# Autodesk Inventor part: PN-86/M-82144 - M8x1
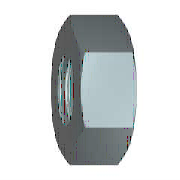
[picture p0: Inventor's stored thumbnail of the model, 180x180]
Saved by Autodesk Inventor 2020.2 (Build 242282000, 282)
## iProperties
Manager: www.cadconsulting.pl
Company: Fabian Stasiak CAD Consulting
Created: 2006-02
Part Number: PN-86/M-82144 - M8x1
Material: Stal, miękka
Description: Nakrętka
Document SubType Name: Modeling
Standard: PN-86/M-82144
Designer: F.Stasiak
Standards Organization: PN
Language: pl-PL
Size Designation: M8x1
Categories: <MemberInstance><Categories><Category DisplayName="Mocowania" InternalName="e4da775c-781d-43d5-af7c-5136215cf5a6" Mnemonic="FSTN"><Category DisplayName="Nakrętk
Density: 7.86 g/cm^3
Mass: 5.74624 g
Surface Area: 6.48179 cm^2
Volume: 0.731074 cm^3
Appearance: Metal-Stal
Author: F.Stasiak
Subject: Zbiór ćwiczeń. Autodesk Inventor 2020. Kurs podstawowy
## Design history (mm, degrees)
sketch "Szkic1"
  geometry: L1 (-7.506, 0)-(-3.753, 6.5); L2 (-3.753, 6.5)-(3.753, 6.5); L3 (3.753, 6.5)-(7.506, 0); L4 (7.506, 0)-(3.753, -6.5); L5 (3.753, -6.5)-(-3.753, -6.5); L6 (-3.753, -6.5)-(-7.506, 0); 2 further points
  constraints: 12 end point, 1 coincident, 1 horizontal, 11 other
  dimensions: "d0" = 15.01111 distance of L3.end L1.start (= 1.1547 x SW)
extrude "Bryła" new body sketch "Szkic1" distance "d1" = 6.8 (= KOH); taper "d2" = 0 deg
sketch "Szkic2"
  geometry: L1 (0, 3.753)-(0, 7.506) reference; L2 (0, 7.506)-(6.8, 7.506) reference; L3 (6.8, 3.753)-(6.8, 7.506) reference; L4 (-0.68, 0)-(8.84, 0) reference; L5 (0.581, 7.506)-(0, 6.5); L6 (6.219, 7.506)-(6.8, 6.5)
  constraints: 4 end point, 4 point on line
  dimensions: "d3" = 30 deg angle of L1 L5 (= ANG1); "d4" = 30 deg angle of L3 L6 (= ANG2); "d5" = 13 diameter of L5.end L4 (= SW0); "d6" = 13 diameter of L6.end L4 (= SW01)
revolve "Faza1" sketch "Szkic2" stored, may be unused: angle "d7" = 90 deg
sketch "Szkic3"
  geometry: A1 r 6.5 centre (0, 0) between (-3.25, -5.629) and (3.25, -5.629) reference; 1 further point
  constraints: 1 coincident
hole "Gwint" sketch "Szkic3" at (0, 0) diameter "d25" = 6.917; stored, may be unused: countersink angle "d29" = 82 deg, drill point angle "d31" = 118 deg; dims "d26" = 6, "d27" = 4, "d28" = 2, "d30" = 8
workaxis "Work Axis1"
workplane "Work Plane1"
node "Bryła1"
node "Korpusy bryłowe"
node "Korpusy powierzchniowe"
chamfer "Faza2" distance "d8" = 0.54127 (= -0.5 x GD1 + 0.5 x NND); stored, may be unused: angle "d9" = 30 deg, second distance "d40" = 0.54127 (= -0.5 x GD1 + 0.5 x NND)
chamfer "Faza3" distance "d10" = 0.54127 (= -0.5 x GD1 + 0.5 x NND); stored, may be unused: angle "d11" = 30 deg, second distance "d41" = 0.54127 (= -0.5 x GD1 + 0.5 x NND)
other parameters: "ANG1" = 30 deg [user parameter; used in 1 equation term], "ANG2" = 30 deg [user parameter; used in 1 equation term], "NND" = 8 [user parameter; used in 4 equation terms], "KOH" = 6.8 [user parameter; used in 1 equation term], "SW" = 13 [user parameter; used in 4 equation terms], "SW0" = 13 (= SW) [user parameter; used in 1 equation term], "SW01" = 13 (= SW) [user parameter; used in 1 equation term], "GD1" = 6.91747 (computed from THREADDIA, PTC, TOA) [user parameter; used in 4 equation terms], "d13" = 0, "d14" = 0, "d39" = 0, "d42" = 0, "GUL" = 0.54127 (= 0.541266 x PTC) [user parameter], "THREADDIA" = 8 [user parameter; used in 1 equation term], "TOA" = 30 deg [user parameter; used in 1 equation term], "PTC" = 1 [user parameter; used in 4 equation terms], "E0" = 15.015 (= 1.155 x SW) [user parameter], "GAL" = 0.54127 (= 0.541266 x PTC) [user parameter]
